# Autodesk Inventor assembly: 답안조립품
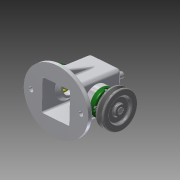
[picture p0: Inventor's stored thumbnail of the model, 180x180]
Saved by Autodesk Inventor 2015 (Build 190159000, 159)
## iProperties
Created: 2017-07
Part Number: 답안조립품
Document SubType Name: Assembly
Designer: C03
Author: C03
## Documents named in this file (15)
- C:\Users\C03\Desktop\470707V1016\답안조립품.iam
- C:\Users\C03\Desktop\470707V1016\본체.ipt
- C:\Users\C03\Desktop\470707V1016\뒤커버.ipt
- C:\Users\C03\Desktop\470707V1016\앞커버.ipt
- C:\Users\C03\Desktop\470707V1016\베어링 12 x 32 x 10.ipt
- C:\Users\C03\Desktop\470707V1016\오일실 12 25 7.ipt
- C:\Users\C03\Desktop\470707V1016\부시.ipt
- C:\Users\C03\Desktop\470707V1016\편심축.ipt
- C:\Users\C03\Desktop\470707V1016\링크.ipt
- C:\Users\C03\Desktop\470707V1016\슬라이드.ipt
- C:\Users\C03\Desktop\470707V1016\핀 5 x 18.ipt
- C:\Users\C03\Desktop\470707V1016\고정핀 1.2 x  8.ipt
- C:\Users\C03\Desktop\470707V1016\볼트 M4 x 12.ipt
- C:\Users\C03\Desktop\470707V1016\키 4 x 4 x 10.ipt
- C:\Users\C03\Desktop\470707V1016\V벨트풀리.ipt
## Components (3 placed, 3 different names)
1. 핀 5 x 18:1
2. 고정핀 1.2 x  8:1
3. V벨트풀리:1
